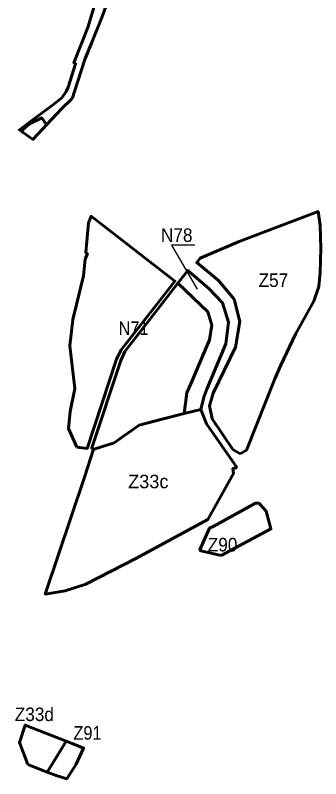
# Model space of a CAD drawing. Extents: x -650277 to -643422, y -1073980 to -1066720.
# Drawn here: x -648572 to -648031, y -1073980 to -1072626 of the extents above; entities that cross this region are included whole.
import ezdxf

# ---------------------------------------------------------------- set-up
doc = ezdxf.new("R2010")
doc.units = 0
doc.header["$LTSCALE"] = 9.6
for name, color, linetype, lineweight in [('24', 7, 'Continuous', 60), ('45', 7, 'Continuous', 60), ('48', 7, 'Continuous', 60), ('5', 7, 'Continuous', 60), ('60', 7, 'Continuous', 60), ('63', 7, 'Continuous', 25), ('9', 7, 'Continuous', 60)]:
    doc.layers.add(name, color=color, linetype=linetype, lineweight=lineweight)

msp = doc.modelspace()

# ---------------------------------------------------------------- linework, layer by layer
at = {"layer": '24'}
for points in [[(-648524.04, -1072809.71), (-648525.08, -1072808.24), (-648547.06, -1072818.59), (-648561.69, -1072831.54), (-648554.22, -1072836.89), (-648541.102, -1072846.281), (-648522.66, -1072826.92), (-648516.44, -1072820.39)], [(-648549.76, -1073954.86), (-648515.333, -1073968.584), (-648498, -1073940), (-648481.749, -1073913.76), (-648554.42, -1073885.092), (-648564.75, -1073915.91)]]:
    msp.add_lwpolyline(points, close=True, dxfattribs=at)
at = {"layer": '45'}
for points in [[(-648463.25, -1073392.125), (-648444.523, -1073394.235), (-648392.43, -1073235.98), (-648384.6, -1073219.54), (-648315.955, -1073131.889), (-648289.148, -1073097.66), (-648437.643, -1072982.601), (-648442.187, -1072994.5), (-648447.043, -1073046.967), (-648444.11, -1073048.69), (-648448.1, -1073058.393)], [(-648448.1, -1073058.393), (-648450.875, -1073088.375), (-648469.875, -1073165.5), (-648475.437, -1073212.375), (-648466.687, -1073288.25), (-648474.5, -1073328.75), (-648477.562, -1073358.875), (-648463.25, -1073392.125)], [(-648272.642, -1073332.558), (-648268, -1073296), (-648261, -1073280), (-648228, -1073202), (-648224, -1073176), (-648231, -1073152), (-648283.884, -1073101.15), (-648311.798, -1073137.127), (-648378.17, -1073222.67), (-648385.09, -1073238.58), (-648436.857, -1073395.099)], [(-648397.062, -1073384.375), (-648378.125, -1073370.875), (-648352.312, -1073353), (-648314.687, -1073343.25), (-648272.642, -1073332.558)], [(-648436.857, -1073395.099), (-648432.187, -1073395.625), (-648397.062, -1073384.375)]]:
    msp.add_lwpolyline(points, dxfattribs=at)
at = {"layer": '48'}
msp.add_lwpolyline([(-648231, -1073152), (-648224, -1073176), (-648228, -1073202), (-648261, -1073280), (-648268, -1073296), (-648272.642, -1073332.558), (-648243.08, -1073325.04), (-648237.98, -1073303.4), (-648232.64, -1073289.31), (-648198.7, -1073209.08), (-648194.2, -1073170.13), (-648205.04, -1073136.07), (-648228.91, -1073110.54), (-648266.38, -1073078.59), (-648283.884, -1073101.15)], close=True, dxfattribs=at)
at = {"layer": '5'}
for points in [[(-648272.642, -1073332.558), (-648352.312, -1073353), (-648397.062, -1073384.375)], [(-648179.07, -1073428.81), (-648233.36, -1073350.68), (-648243.08, -1073325.04), (-648272.642, -1073332.558)], [(-648397.062, -1073384.375), (-648432.187, -1073395.625), (-648433.206, -1073395.51), (-648449.599, -1073445.278)], [(-648447.06, -1073635.39), (-648358.69, -1073589.35), (-648230.81, -1073520.18), (-648185.34, -1073438.91), (-648185.82, -1073435.12), (-648186.46, -1073430.01), (-648183.46, -1073429.52), (-648179.07, -1073428.81)], [(-648449.599, -1073445.278), (-648518.867, -1073652.836), (-648483.58, -1073646.7), (-648447.06, -1073635.39), (-648447.06, -1073635.39)]]:
    msp.add_lwpolyline(points, dxfattribs=at)
at = {"layer": '60'}
msp.add_line((-648245.341, -1073575.152), (-648207, -1073584), dxfattribs=at)
for points in [[(-648432.45, -1072610.56), (-648443.77, -1072648.02), (-648468.01, -1072710.44), (-648465.25, -1072712.03), (-648478.58, -1072753.49), (-648481.62, -1072761.39), (-648489.76, -1072772.74), (-648506.1, -1072785.56), (-648542.43, -1072812.6), (-648564.86, -1072829.45), (-648561.69, -1072831.54), (-648547.06, -1072818.59), (-648525.08, -1072808.24), (-648524.04, -1072809.71), (-648516.44, -1072820.39), (-648489.69, -1072791.37), (-648473.13, -1072775.58), (-648470.89, -1072772.42), (-648467.286, -1072761.426), (-648448.58, -1072704.37), (-648436.75, -1072675.79), (-648418.45, -1072629.91), (-648409.08, -1072604.25)], [(-648139.56, -1073491.4), (-648146.4, -1073491.55), (-648220.42, -1073532.43), (-648227.63, -1073535.89), (-648245.341, -1073575.152)], [(-648207, -1073584), (-648119, -1073537), (-648127.31, -1073505.75), (-648138.41, -1073493.62), (-648139.56, -1073491.4)]]:
    msp.add_lwpolyline(points, dxfattribs=at)
msp.add_lwpolyline([(-648515.333, -1073968.584), (-648499.84, -1073974.76), (-648480.86, -1073980.25), (-648464.44, -1073954.69), (-648451.05, -1073925.87), (-648471, -1073918), (-648481.749, -1073913.76)], close=True, dxfattribs=at)
at = {"layer": '63'}
msp.add_lwpolyline([(-648254, -1073034), (-648295, -1073034), (-648250, -1073112)], dxfattribs=at)
at = {"layer": '9'}
for points in [[(-648030.86, -1073039.71), (-648032.09, -1072998.65), (-648035.592, -1072974.222), (-648175.061, -1073027.551), (-648244.214, -1073056.657), (-648250.491, -1073064.698), (-648212.22, -1073096.39), (-648184.37, -1073129.89)], [(-648101.67, -1073246.63), (-648075.34, -1073191.93), (-648043.29, -1073132.97), (-648034.43, -1073107.07), (-648031.8, -1073082.07), (-648030.86, -1073039.71)], [(-648184.37, -1073129.89), (-648174.03, -1073168.94), (-648182.12, -1073214.56), (-648221.39, -1073296.24), (-648227.75, -1073318.75), (-648223.03, -1073341.59), (-648186.47, -1073396.47), (-648173.38, -1073404.03)], [(-648173.38, -1073404.03), (-648162.55, -1073397.4), (-648112.36, -1073270.87), (-648101.67, -1073246.63)]]:
    msp.add_lwpolyline(points, dxfattribs=at)

# ---------------------------------------------------------------- texts
at = {"layer": '63'}
for s, width, p in [('N78', 0.95, (-648314, -1073028)), ('Z57', 0.95, (-648141, -1073108)), ('N71', 0.9, (-648389, -1073193)), ('Z90', 0.95, (-648231, -1073577)), ('Z33d', 0.95, (-648573, -1073878)), ('Z91', 0.9, (-648469, -1073911))]:
    msp.add_text(s, height=24, dxfattribs=dict(at, width=width)).set_placement(p)
msp.add_text('Z33c', height=24, dxfattribs=at).set_placement((-648372, -1073465))

doc.saveas('drawing.dxf')
